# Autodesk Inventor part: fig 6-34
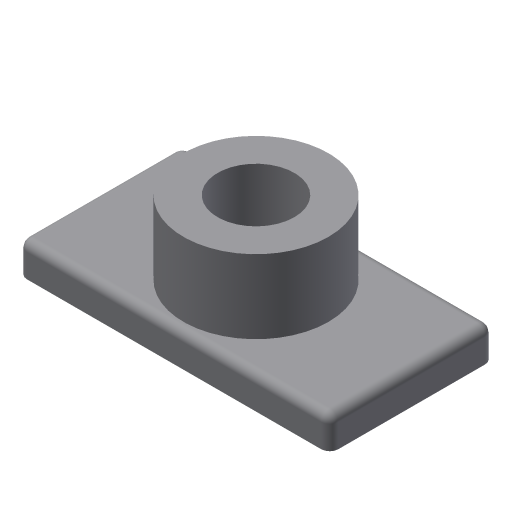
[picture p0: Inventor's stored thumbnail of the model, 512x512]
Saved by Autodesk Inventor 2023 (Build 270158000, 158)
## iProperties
Created: 2004-05
Part Number: fig 6-34
Document SubType Name: Modeling
Designer: CADCIM Technologies
Manufacturer: Standard
Standards Organization: Custom
Density: 1 g/cm^3
Material: Generic
Appearance: Default
Author: CADCIM Technologies
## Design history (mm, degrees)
sketch "Sketch1"
  geometry: L1 (-39.276, -18.692)-(33.721, -18.692); L2 (33.721, -18.692)-(33.721, 19.728); L3 (33.721, 19.728)-(-39.276, 19.728); L4 (-39.276, 19.728)-(-39.276, -18.692)
  constraints: 8 end point, 2 parallel, 1 horizontal, 1 perpendicular
extrude "Extrusion1" new body sketch "Sketch1" distance "d0" = 7.5; taper "d1" = 0 deg
sketch "Sketch2"
  geometry: C1 r 17 at (-2.778, 0.518)
  constraints: 1 centre point
  dimensions: "d16" = 34 diameter of C1
extrude "Extrusion2" join sketch "Sketch2" distance "d3" = 17.25; taper "d4" = 0 deg
hole "Hole1" diameter "d8" = 18; stored, may be unused: countersink angle "d12" = 90 deg, drill point angle "d14" = 118 deg; dims "d6" = 10, "d7" = 10, "d9" = 6, "d10" = 4, "d11" = 2, "d13" = 8
fillet "Fillet4" dims "d17" = 2
body "Solid1"
